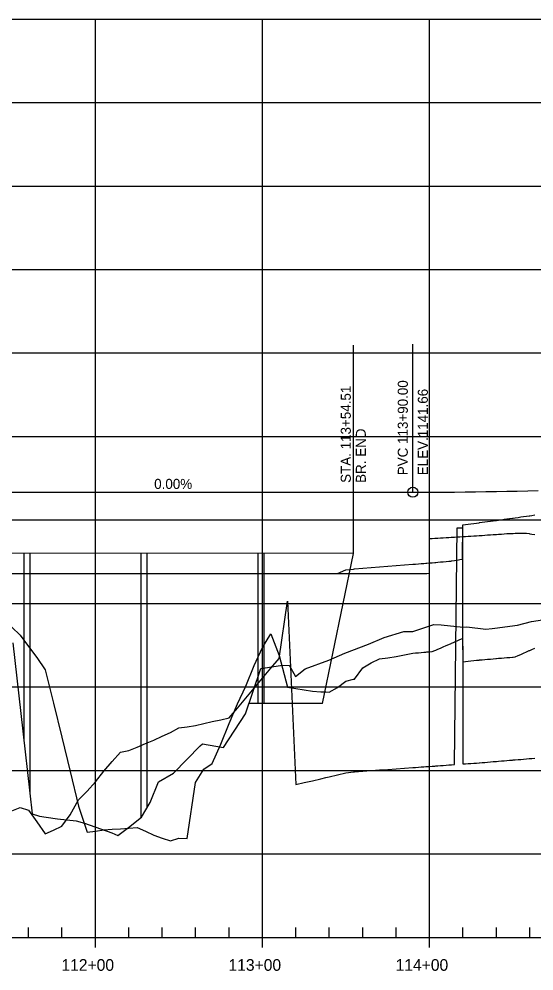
# Model space of a CAD drawing. Extents: x 688474 to 694748, y 765018 to 767373.
# Drawn here: x 692108 to 692416, y 765790 to 766360 of the extents above; entities that cross this region are included whole.
import ezdxf

# ---------------------------------------------------------------- set-up
doc = ezdxf.new("R2010")
doc.units = 0
for name, color, linetype in [('30', 7, 'Continuous'), ('37', 7, 'Continuous'), ('BRIDGE', 7, 'Continuous'), ('R_Exist Surface', 7, 'Continuous'), ('R_Profile Work Left', 7, 'Continuous'), ('R_Profile Work Right', 7, 'Continuous'), ('R_Vert Alg', 7, 'Continuous'), ('R_Vert Alg Annot', 7, 'Continuous')]:
    doc.layers.add(name, color=color, linetype=linetype)

msp = doc.modelspace()

# ---------------------------------------------------------------- linework, layer by layer
at = {"layer": '37'}
for p, q in [((690853.59, 766359.92), (693453.59, 766359.92)), ((690853.59, 766359.92), (693453.59, 766359.92)), ((692153.59, 765809.92), (692153.59, 766359.92)), ((692253.59, 765809.92), (692253.59, 766359.92)), ((692353.59, 765809.92), (692353.59, 766359.92)), ((690853.59, 766309.92), (693453.59, 766309.92)), ((690853.59, 766259.92), (693453.59, 766259.92)), ((690853.59, 766209.92), (693453.59, 766209.92)), ((690853.59, 766159.92), (693453.59, 766159.92)), ((690853.59, 766109.92), (693453.59, 766109.92)), ((690853.59, 766059.92), (693453.59, 766059.92)), ((690853.59, 766009.92), (693453.59, 766009.92)), ((690853.59, 765959.92), (693453.59, 765959.92)), ((690853.59, 765909.92), (693453.59, 765909.92)), ((690853.59, 765859.92), (693453.59, 765859.92)), ((692113.59, 765809.92), (692113.59, 765815.92)), ((692133.59, 765809.92), (692133.59, 765815.92)), ((692173.59, 765809.92), (692173.59, 765815.92)), ((692193.59, 765809.92), (692193.59, 765815.92)), ((692213.59, 765809.92), (692213.59, 765815.92)), ((692233.59, 765809.92), (692233.59, 765815.92)), ((692273.59, 765809.92), (692273.59, 765815.92)), ((692293.59, 765809.92), (692293.59, 765815.92)), ((692313.59, 765809.92), (692313.59, 765815.92)), ((692333.59, 765809.92), (692333.59, 765815.92)), ((692373.59, 765809.92), (692373.59, 765815.92)), ((692393.59, 765809.92), (692393.59, 765815.92)), ((692413.59, 765809.92), (692413.59, 765815.92)), ((690853.59, 765809.92), (693453.59, 765809.92)), ((692153.59, 765803.92), (692153.59, 765809.92)), ((692253.59, 765803.92), (692253.59, 765809.92)), ((692353.59, 765803.92), (692353.59, 765809.92))]:
    msp.add_line(p, q, dxfattribs=at)
at = {"layer": 'BRIDGE'}
for p, q in [((692308.1, 766076.52), (692308.1, 766164.58)), ((692308.1, 766039.92), (692308.1, 766076.52)), ((692308.1, 766039.92), (692057.07, 766039.94)), ((692110.84, 766039.93), (692110.84, 765927.22)), ((692114.34, 766039.93), (692114.34, 765896.24)), ((692180.84, 766039.93), (692180.84, 765881.62)), ((692184.34, 766039.93), (692184.34, 765887.27)), ((692250.84, 766039.92), (692250.84, 765949.92)), ((692254.34, 766039.92), (692254.34, 765949.92)), ((692289.46, 765949.92), (692308.1, 766039.92)), ((692289.46, 765949.92), (692245.61, 765949.92))]:
    msp.add_line(p, q, dxfattribs=at)
at = {"layer": 'R_Exist Surface'}
msp.add_lwpolyline([(692104.27, 765986.41), (692110.15, 765933.44), (692115.73, 765883.85), (692120.24, 765882.44), (692129.6, 765881.07), (692130.89, 765880.92), (692142.13, 765879.64), (692147.07, 765878.26), (692163.35, 765872.54), (692167.08, 765870.92), (692173.43, 765875.76), (692181.28, 765881.96), (692186.31, 765890.7), (692191.36, 765903.11), (692200.4, 765908.26), (692216.34, 765924.65), (692217.75, 765925.84), (692230.3, 765923.66), (692243.52, 765943.74), (692252.72, 765971.02), (692264.46, 765972.83), (692269.49, 765972.96), (692273.3, 765966.26), (692279.11, 765970.79), (692293.24, 765975.99), (692302.8, 765980.19), (692317.08, 765985.55), (692326.49, 765989.59), (692338.13, 765993.14), (692343.55, 765993.07), (692356.11, 765997.25), (692360.65, 765997.09), (692373.66, 765995.81), (692375.87, 765995.94), (692387.2, 765994.49), (692391.14, 765994.83), (692392.73, 765995.18), (692406.29, 765996.87), (692414.55, 765999.07), (692421.2, 766000.18)], dxfattribs=at)
at = {"layer": 'R_Profile Work Left'}
for points in [[(692103.59, 766027.85), (692108.59, 766027.85), (692113.59, 766027.85), (692118.59, 766027.85), (692123.59, 766027.85), (692128.59, 766027.85), (692133.59, 766027.85), (692138.59, 766027.85), (692143.59, 766027.85), (692148.59, 766027.85), (692153.59, 766027.85), (692158.59, 766027.85), (692163.59, 766027.85), (692168.59, 766027.85), (692173.59, 766027.85), (692178.59, 766027.85), (692183.59, 766027.85), (692188.59, 766027.85), (692193.59, 766027.85), (692198.59, 766027.85), (692203.59, 766027.85), (692208.59, 766027.85), (692213.59, 766027.85), (692218.59, 766027.85), (692223.59, 766027.85), (692228.59, 766027.85), (692233.59, 766027.85), (692238.59, 766027.85), (692243.59, 766027.85), (692248.59, 766027.85), (692253.59, 766027.85), (692258.59, 766027.85), (692263.59, 766027.85), (692268.59, 766027.85), (692273.59, 766027.85), (692278.59, 766027.85), (692283.59, 766027.85), (692288.59, 766027.85), (692291.47, 766027.85), (692293.59, 766027.85), (692298.59, 766027.85), (692303.59, 766030.15), (692308.1, 766030.52), (692308.59, 766030.56), (692313.59, 766030.96), (692318.59, 766031.36), (692323.59, 766031.77), (692328.59, 766032.17), (692333.59, 766032.57), (692338.59, 766032.98), (692343.59, 766033.38), (692345.25, 766033.52), (692346.9, 766033.65), (692348.56, 766033.79), (692348.59, 766033.79), (692350.22, 766033.92), (692351.31, 766034.01), (692351.88, 766034.06), (692353.53, 766034.2), (692353.59, 766034.21), (692355.19, 766034.34), (692356.85, 766034.48), (692357.29, 766034.52), (692358.51, 766034.63), (692360.16, 766034.77), (692361.82, 766034.91), (692363.48, 766035.06), (692363.59, 766035.07), (692365.14, 766035.21), (692366.57, 766035.33), (692366.79, 766035.37), (692368.45, 766035.63), (692368.59, 766035.65), (692370.11, 766035.89), (692371.76, 766036.15), (692373.42, 766036.41), (692373.59, 766057.04), (692375.08, 766057.22), (692376.74, 766057.44), (692378.39, 766057.65), (692380.05, 766057.86), (692381.71, 766058.08), (692383.37, 766058.29), (692383.59, 766058.32), (692385.02, 766058.51), (692386.68, 766058.73), (692388.34, 766058.95), (692390, 766059.17), (692391.65, 766059.4), (692393.31, 766059.62), (692393.59, 766059.66), (692394.97, 766059.85), (692396.63, 766060.08), (692398.28, 766060.31), (692399.94, 766060.54), (692401.38, 766060.74), (692401.6, 766060.77), (692403.26, 766061), (692403.59, 766061.05), (692404.91, 766061.24), (692406.57, 766061.47), (692408.23, 766061.71), (692409.89, 766061.95), (692411.54, 766062.19), (692413.2, 766062.43), (692413.59, 766062.49), (692414.86, 766062.67), (692416.52, 766062.92)], [(692103.59, 765995.69), (692108.59, 765990.88), (692113.59, 765984.2), (692118.59, 765977.52), (692123.59, 765970.18), (692128.59, 765950.15), (692133.59, 765929.89), (692138.59, 765909.36), (692143.59, 765888.6), (692148.59, 765872.92), (692153.59, 765873.64), (692158.59, 765874.37), (692163.59, 765874.74), (692168.59, 765875.04), (692173.59, 765875.33), (692178.59, 765875.79), (692183.59, 765873.45), (692188.59, 765871.11), (692193.59, 765869.31), (692198.59, 765867.83), (692203.59, 765869.45), (692208.59, 765869.17), (692213.59, 765902.66), (692218.59, 765910.71), (692223.59, 765914.13), (692228.59, 765925.7), (692233.59, 765937.98), (692238.59, 765949.75), (692243.59, 765960.39), (692248.59, 765972.71), (692253.59, 765983.52), (692258.59, 765991.63), (692263.59, 765978.73), (692268.59, 765959.79), (692273.59, 765959), (692278.59, 765958.21), (692283.59, 765957.42), (692288.59, 765956.97), (692291.47, 765956.92), (692293.59, 765956.88), (692298.59, 765959.59), (692303.59, 765963.43), (692308.1, 765964.64), (692308.59, 765964.57), (692313.59, 765971.4), (692318.59, 765974.34), (692323.59, 765976.84), (692328.59, 765977.45), (692333.59, 765978.05), (692338.59, 765979.16), (692343.59, 765980.14), (692345.25, 765980.29), (692346.9, 765980.44), (692348.56, 765980.59), (692348.59, 765980.59), (692350.22, 765980.74), (692351.31, 765980.83), (692351.88, 765980.88), (692353.53, 765981.03), (692353.59, 765981.04), (692355.19, 765981.18), (692356.85, 765981.73), (692357.29, 765981.93), (692358.51, 765982.46), (692360.16, 765983.2), (692361.82, 765983.93), (692363.48, 765984.66), (692363.59, 765984.71), (692365.14, 765985.39), (692366.57, 765986.02), (692366.79, 765986.12), (692368.45, 765986.83), (692368.59, 765986.89), (692370.11, 765987.54), (692371.76, 765988.25), (692373.42, 765988.83), (692373.59, 765975.03), (692375.08, 765975.16), (692376.74, 765975.34), (692378.39, 765975.51), (692380.05, 765975.69), (692381.71, 765975.86), (692383.37, 765976.04), (692383.59, 765976.06), (692385.02, 765976.21), (692386.68, 765976.35), (692388.34, 765976.49), (692390, 765976.62), (692391.65, 765976.76), (692393.31, 765976.92), (692393.59, 765976.94), (692394.97, 765977.08), (692396.63, 765977.24), (692398.28, 765977.35), (692399.94, 765977.47), (692401.38, 765977.57), (692401.6, 765977.59), (692403.26, 765977.7), (692403.59, 765977.73), (692404.91, 765977.95), (692406.57, 765978.65), (692408.23, 765979.42), (692409.89, 765980.18), (692411.54, 765980.92), (692413.2, 765981.66), (692413.59, 765981.83), (692414.86, 765982.4), (692416.52, 765983.15)]]:
    msp.add_lwpolyline(points, dxfattribs=at)
at = {"layer": 'R_Profile Work Right'}
for points in [[(692268.59, 766011.26), (692273.59, 765901.49), (692278.59, 765902.63), (692283.59, 765903.78), (692288.59, 765904.93), (692291.47, 765905.59), (692293.59, 765906.08), (692298.59, 765907.23), (692303.59, 765908.38), (692308.1, 765909.07), (692308.59, 765909.1), (692313.59, 765909.46), (692318.59, 765909.82), (692323.59, 765910.18), (692328.59, 765910.54), (692333.59, 765910.9), (692338.59, 765911.26), (692343.59, 765911.62), (692345.25, 765911.74), (692346.9, 765911.86), (692348.56, 765911.98), (692348.59, 765911.98), (692350.22, 765912.1), (692351.31, 765912.18), (692351.88, 765912.22), (692353.53, 765912.34), (692353.59, 765912.34), (692355.19, 765912.46), (692356.85, 765912.57), (692357.29, 765912.61), (692358.51, 765912.69), (692360.16, 765912.81), (692361.82, 765912.93), (692363.48, 765913.05), (692363.59, 765913.06), (692365.14, 765913.17), (692366.57, 765913.27), (692366.79, 765913.29), (692368.45, 765913.41), (692368.59, 765913.42), (692370.11, 766055.28)], [(692370.11, 766055.28), (692371.76, 766055.28), (692373.42, 766055.28)], [(692373.42, 766055.28), (692373.59, 765913.78), (692375.08, 765913.89), (692376.74, 765914), (692378.39, 765914.12), (692380.05, 765914.24), (692381.71, 765914.36), (692383.37, 765914.48), (692383.59, 765914.5), (692385.02, 765914.61), (692386.68, 765914.75), (692388.34, 765914.89), (692390, 765915.03), (692391.65, 765915.17), (692393.31, 765915.31), (692393.59, 765915.33), (692394.97, 765915.45), (692396.63, 765915.59), (692398.28, 765915.73), (692399.94, 765915.87), (692401.38, 765915.99), (692401.6, 765916.01), (692403.26, 765916.15), (692403.59, 765916.17), (692404.91, 765916.29), (692406.57, 765916.43), (692408.23, 765916.56), (692409.89, 765916.7), (692411.54, 765916.84), (692413.2, 765916.98), (692413.59, 765917.01), (692414.86, 765917.12), (692416.52, 765917.26)], [(692103.59, 766027.85), (692108.59, 766027.85), (692113.59, 766027.85), (692118.59, 766027.85), (692123.59, 766027.85), (692128.59, 766027.85), (692133.59, 766027.85), (692138.59, 766027.85), (692143.59, 766027.85), (692148.59, 766027.85), (692153.59, 766027.85), (692158.59, 766027.85), (692163.59, 766027.85), (692168.59, 766027.85), (692173.59, 766027.85), (692178.59, 766027.85), (692183.59, 766027.85), (692188.59, 766027.85), (692193.59, 766027.85), (692198.59, 766027.85), (692203.59, 766027.85), (692208.59, 766027.85), (692213.59, 766027.85), (692218.59, 766027.85), (692223.59, 766027.85), (692228.59, 766027.85), (692233.59, 766027.85), (692238.59, 766027.85), (692243.59, 766027.85), (692248.59, 766027.85), (692253.59, 766027.85), (692258.59, 766027.85), (692263.59, 766027.85), (692268.59, 766027.85), (692273.59, 766027.85), (692278.59, 766027.85), (692283.59, 766027.85), (692288.59, 766027.85), (692291.47, 766027.85), (692293.59, 766027.85), (692298.59, 766027.85), (692303.59, 766027.85), (692308.1, 766027.85), (692308.59, 766027.85), (692313.59, 766027.85), (692318.59, 766027.85), (692323.59, 766027.85), (692328.59, 766027.85), (692333.59, 766027.85), (692338.59, 766027.85), (692343.59, 766027.85), (692345.25, 766027.85), (692346.9, 766027.85), (692348.56, 766027.85), (692348.59, 766027.85), (692350.22, 766027.86), (692351.31, 766027.86), (692351.88, 766027.93), (692353.53, 766028.13), (692353.59, 766048.81), (692355.19, 766048.9), (692356.85, 766048.99), (692357.29, 766049.02), (692358.51, 766049.09), (692360.16, 766049.18), (692361.82, 766049.27), (692363.48, 766049.37), (692363.59, 766049.38), (692365.14, 766049.47), (692366.57, 766049.55), (692366.79, 766049.56), (692368.45, 766049.66), (692368.59, 766049.67), (692370.11, 766049.76), (692371.76, 766049.86), (692373.42, 766049.97), (692373.59, 766049.98), (692375.08, 766050.07), (692376.74, 766050.17), (692378.39, 766050.28), (692380.05, 766050.38), (692381.71, 766050.49), (692383.37, 766050.6), (692383.59, 766050.61), (692385.02, 766050.71), (692386.68, 766050.82), (692388.34, 766050.93), (692390, 766051.04), (692391.65, 766051.15), (692393.31, 766051.27), (692393.59, 766051.29), (692394.97, 766051.38), (692396.63, 766051.5), (692398.28, 766051.62), (692399.94, 766051.73), (692401.38, 766051.84), (692401.6, 766051.84), (692403.26, 766051.88), (692403.59, 766051.89), (692404.91, 766051.92), (692406.57, 766051.95), (692408.23, 766051.99), (692409.89, 766052.03), (692411.54, 766052.04), (692413.2, 766051.73), (692413.59, 766051.66), (692414.86, 766051.43), (692416.52, 766051.12)], [(692103.59, 765885.82), (692108.59, 765887.81), (692113.59, 765886.12), (692118.59, 765879.07), (692123.59, 765871.87), (692128.59, 765874.23), (692133.59, 765876.59), (692138.59, 765883.28), (692143.59, 765892.38), (692148.59, 765897.57), (692153.59, 765903.18), (692158.59, 765909.47), (692163.59, 765915.28), (692168.59, 765920.9), (692173.59, 765921.94), (692178.59, 765923.8), (692183.59, 765925.97), (692188.59, 765928.14), (692193.59, 765930.36), (692198.59, 765932.6), (692203.59, 765935.5), (692208.59, 765936.03), (692213.59, 765936.76), (692218.59, 765937.95), (692223.59, 765939.13), (692228.59, 765940.31), (692233.59, 765941.5), (692238.59, 765947.18), (692243.59, 765953.15), (692248.59, 765959.12), (692253.59, 765965.1), (692258.59, 765971.07), (692263.59, 765977.04), (692268.59, 766011.26)]]:
    msp.add_lwpolyline(points, dxfattribs=at)
at = {"layer": 'R_Vert Alg'}
msp.add_line((692061.59, 766076.52), (692343.59, 766076.52), dxfattribs=at)
msp.add_lwpolyline([(692343.59, 766076.52), (692349.84, 766076.53), (692356.09, 766076.55), (692362.34, 766076.59), (692368.59, 766076.64), (692374.84, 766076.7), (692381.09, 766076.78), (692387.34, 766076.88), (692393.59, 766076.98), (692399.84, 766077.11), (692406.09, 766077.24), (692412.34, 766077.4), (692418.59, 766077.56)], dxfattribs=at)
msp.add_circle((692343.59, 766076.52), 3, dxfattribs=at)
at = {"layer": 'R_Vert Alg Annot'}
msp.add_line((692343.59, 766076.52), (692343.59, 766165.27), dxfattribs=at)

# ---------------------------------------------------------------- texts
at = {"layer": '30'}
for s, p in [('112+00', (692133.28, 765789.92)), ('113+00', (692233.28, 765789.92)), ('114+00', (692333.28, 765789.92))]:
    msp.add_text(s, height=7, dxfattribs=at).set_placement(p)
at = {"layer": 'BRIDGE'}
for s, p in [('STA. 113+54.51', (692306.48, 766082.13)), ('BR. END', (692315.48, 766082.13))]:
    msp.add_text(s, height=6, rotation=90, dxfattribs=at).set_placement(p)
at = {"layer": 'R_Vert Alg Annot'}
for s, rotation, p in [('PVC 113+90.00', 90, (692340.59, 766086.71)), ('ELEV.1141.66', 90, (692352.59, 766086.71)), ('0.00%', 360, (692188.79, 766078.52))]:
    msp.add_text(s, height=6, rotation=rotation, dxfattribs=at).set_placement(p)

doc.saveas('drawing.dxf')
